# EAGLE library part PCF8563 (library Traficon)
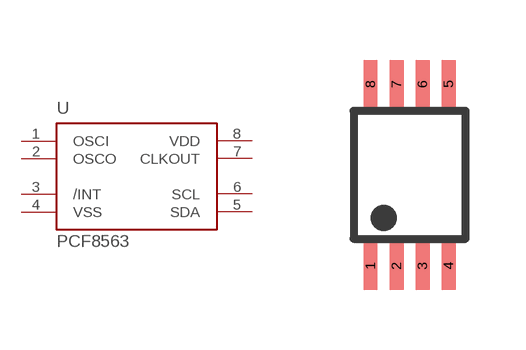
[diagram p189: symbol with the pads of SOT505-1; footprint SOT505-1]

Designator prefix U

## PCF8563TS  [SOT505-1]
1  OSCI
2  OSCO
3  /INT
4  VSS
5  SDA
6  SCL
7  CLKOUT
8  VDD

## Footprint SOT505-1 (pad centres in mm)
CT: 7 oct. 2008: changed package name + checked pad layout with NXP sot505-1.
smd 0.35 x 1.2: 1 -0.975,-2.275; 2 -0.325,-2.275; 3 0.325,-2.275; 4 0.975,-2.275; 5 0.975,2.275; 6 0.325,2.275; 7 -0.325,2.275; 8 -0.975,2.275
